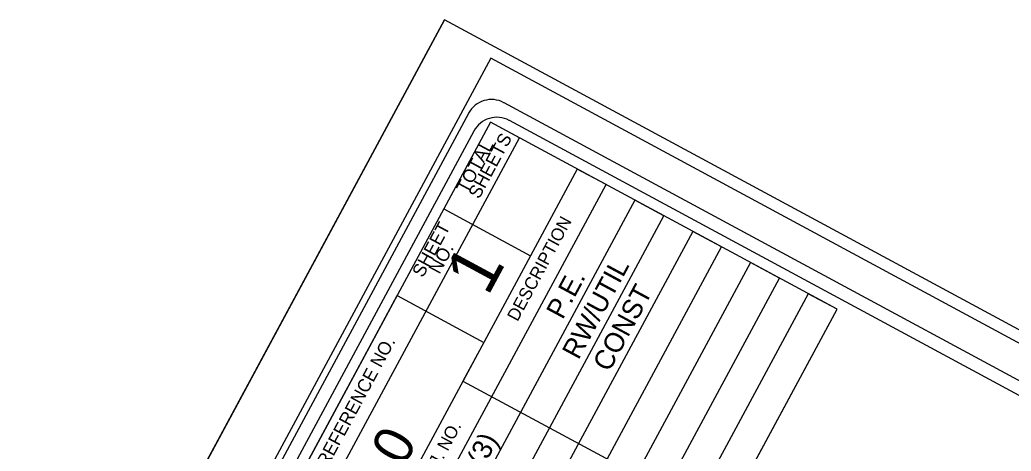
# Model space of a CAD drawing. Extents: x 1376167 to 1379209, y 761324 to 763997.
# Drawn here: x 1376804.3 to 1377182, y 763833.3 to 763997.5 of the extents above; entities that cross this region are included whole.
import ezdxf

# ---------------------------------------------------------------- set-up
doc = ezdxf.new("R2010")
doc.units = 0
for name, color, linetype in [('Sheet Cutting Line CELL', 7, 'Continuous'), ('Sheet Data Field CELL', 7, 'Continuous'), ('Sheet Plot Border Inside CELL', 7, 'Continuous'), ('Sheet Plot Border Outside CELL', 7, 'Continuous'), ('Sheet Title CELL', 7, 'Continuous')]:
    doc.layers.add(name, color=color, linetype=linetype)

msp = doc.modelspace()

# ---------------------------------------------------------------- linework, layer by layer
at = {"layer": 'Sheet Cutting Line CELL'}
msp.add_line((1376166.94, 762515.18), (1376966.07, 763997.49), dxfattribs=at)
at = {"layer": 'Sheet Plot Border Inside CELL'}
msp.add_lwpolyline([(1377121.6, 762015.28), (1377912.43, 763482.18), (1376983.7, 763982.88), (1376192.87, 762515.97)], close=True, dxfattribs=at)
at = {"layer": 'Sheet Plot Border Outside CELL'}
msp.add_lwpolyline([(1376966.07, 763997.49), (1376166.94, 762515.18), (1377135.18, 761993.19), (1377934.31, 763475.5)], close=True, dxfattribs=at)
at = {"layer": 'Sheet Title CELL'}
for points in [[(1377895.44, 763477.14), (1376988.81, 763965.92)], [(1376975.27, 763961.87), (1376272.92, 762659.12)], [(1376864.15, 763710.48), (1376994.65, 763952.55), (1376983.65, 763958.48), (1376853.16, 763716.41)], [(1376870.94, 763749.42), (1376948.08, 763892.47), (1376981.07, 763874.66), (1376973.14, 763859.96), (1377072.17, 763806.58), (1377115.68, 763887.3), (1376983.65, 763958.48), (1376965.85, 763925.47), (1376998.87, 763907.68)], [(1377725.83, 763562.9), (1376990.83, 763959.15)], [(1376977.29, 763955.09), (1376303.44, 762705.17)], [(1376897.17, 763692.68), (1377027.67, 763934.74), (1377016.66, 763940.68), (1376886.16, 763698.62)], [(1376919.18, 763680.82), (1377049.67, 763922.89), (1377038.67, 763928.81), (1376908.17, 763686.75)], [(1376941.17, 763668.96), (1377071.67, 763911.02), (1377060.67, 763916.95), (1376930.17, 763674.89)], [(1376963.19, 763657.09), (1377093.69, 763899.15), (1377082.69, 763905.09), (1376952.19, 763663.03)], [(1376985.18, 763645.23), (1377115.68, 763887.3), (1377104.69, 763893.22), (1376974.18, 763651.16)]]:
    msp.add_lwpolyline(points, dxfattribs=at)
for centre in [(1376984.02, 763957.15), (1376986.05, 763950.37)]:
    msp.add_arc(centre, 10, 61.6702, 151.6702, dxfattribs=at)

# ---------------------------------------------------------------- texts
at = {"layer": 'Sheet Data Field CELL'}
for s, height, p in [('RW/UTIL', 7.5, (1377017.15, 763867.73)), ('P.E.', 7.5, (1377011.11, 763883.05)), ('CONST', 7.5, (1377028.85, 763863.09)), ('B-5110', 15, (1376925.25, 763779.95)), ('BRZ-1626(3)', 7.5, (1376959.2, 763786.56))]:
    msp.add_text(s, height=height, rotation=61.6702, dxfattribs=at).set_placement(p)
at = {"layer": 'Sheet Title CELL'}
for s, height, p in [('SHEETS', 5, (1376979.29, 763929)), ('TOTAL', 5, (1376974.73, 763931.08)), ('SHEET', 5, (1376957.87, 763899.04)), ('DESCRIPTION', 4.8, (1376993.91, 763882.34)), ('NO.', 5, (1376964.19, 763900.35)), ('1', 19.35, (1376982.56, 763891.87)), ('STATE PROJECT REFERENCE NO.', 4.9998, (1376894.67, 763777.08)), ('F. A. PROJ. NO.', 4.8, (1376950.19, 763801.28))]:
    msp.add_text(s, height=height, rotation=61.6702, dxfattribs=at).set_placement(p)

doc.saveas('drawing.dxf')
